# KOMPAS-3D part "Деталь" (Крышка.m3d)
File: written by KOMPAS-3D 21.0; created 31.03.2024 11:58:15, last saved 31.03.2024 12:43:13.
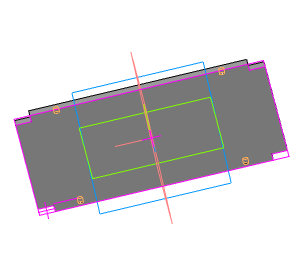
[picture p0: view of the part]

Document properties: Автор: Школа; Полное имя файла: C:\Users\Школа\Desktop\КУБСАТ ПРЕДПРОФФ\Крышка.m3d

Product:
- Part/product: Деталь
    Масса: 0.139417

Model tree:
1. Эскиз:1
2. Элемент выдавливания:1
     Расстояние 1 = 2
3. Эскиз:2  (with: Элемент выдавливания:1)
4. Отверстие:1  (with: Элемент выдавливания:1)  (labels: M2)
     Глубина выреза = 2; Диаметр отверстия = 1.56699; Угол конуса дна = 118; Расстояние 1 = 79; Расстояние 2 = -3
5. M2  (with: Элемент выдавливания:1)  (labels: cil0_24705-2004 coarse)
     Длина резьбы = 2; Шаг резьбы = 0.4; Номинальный диаметр резьбы = 2
6. Зеркальный массив:1
7. Экземпляр ( 1 )
8. Экземпляр ( 2 )  (with: Отверстие:1)
9. Зеркальный массив:2  (with: Экземпляр ( 1 ), Экземпляр ( 2 ), Зеркальный массив:1, Отверстие:1)
10. Экземпляр ( 2 )  (with: Отверстие:1)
